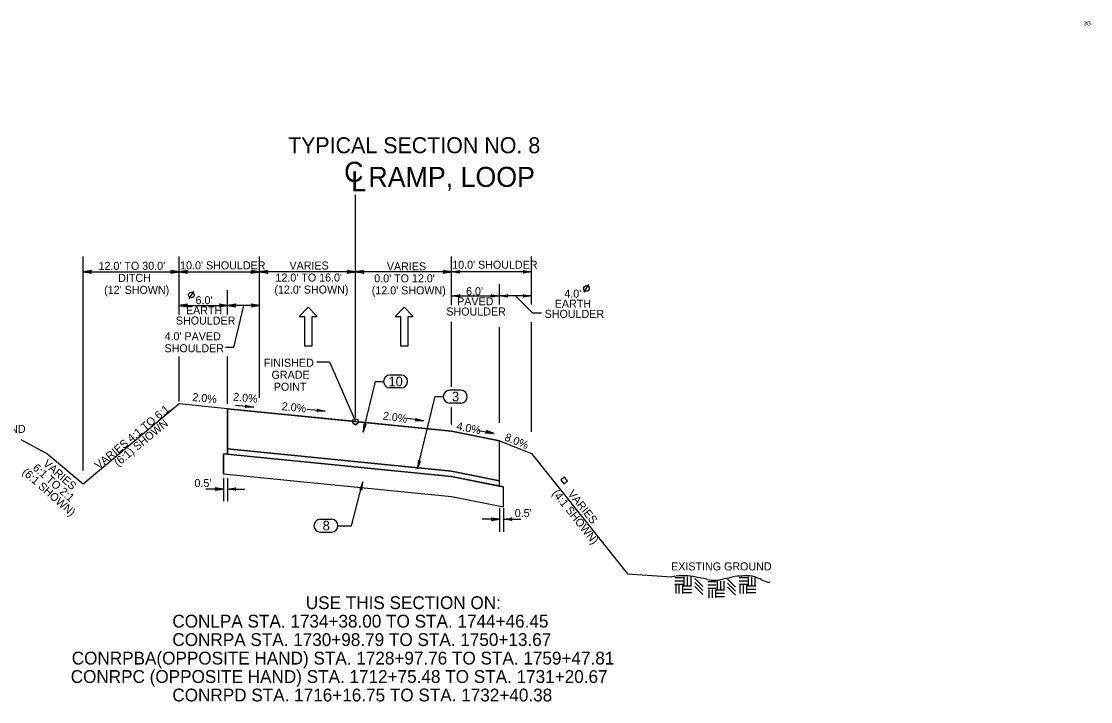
# Model space of a CAD drawing. Extents: x 2003207 to 2014043, y 843846 to 860154.
# Drawn here: x 2013648.6 to 2013782.2, y 844104.4 to 844189.4 of the extents above; entities that cross this region are included whole.
import ezdxf

# ---------------------------------------------------------------- set-up
doc = ezdxf.new("R2010")
doc.units = 0
for name, color, linetype in [('RD_EX_Pavement_Markings', 7, 'Continuous'), ('RD_EX_Road_txCode', 7, 'Continuous'), ('RD_QTY_Base_Course', 7, 'Continuous'), ('RD_QTY_ConcPave', 7, 'Continuous'), ('RD_QTY_Intermediate', 7, 'Continuous'), ('RD_QTY_PermVeg', 7, 'Continuous'), ('RD_QTY_Surf_Course', 7, 'Continuous'), ('RD_SHT_TX', 7, 'Continuous'), ('RD_TX_Misc1', 7, 'Continuous'), ('RD_TX_Misc2', 7, 'Continuous'), ('RD_TX_TypSect', 7, 'Continuous'), ('RD_XS_ExGround', 7, 'Continuous')]:
    doc.layers.add(name, color=color, linetype=linetype)

msp = doc.modelspace()

# ---------------------------------------------------------------- linework, layer by layer
at = {"layer": 'RD_EX_Pavement_Markings'}
for points in [[(2013683.94, 844148.88), (2013684.9, 844148.88), (2013684.9, 844152.54), (2013685.55, 844152.54), (2013684.42, 844153.68), (2013683.29, 844152.54), (2013683.94, 844152.54)], [(2013695.94, 844148.88), (2013696.9, 844148.88), (2013696.9, 844152.54), (2013697.55, 844152.54), (2013696.42, 844153.68), (2013695.29, 844152.54), (2013695.94, 844152.54)]]:
    msp.add_lwpolyline(points, close=True, dxfattribs=at)
at = {"layer": 'RD_EX_Road_txCode'}
msp.add_lwpolyline([(2013715.97, 844132.11), (2013716.35, 844131.64), (2013716.82, 844132.01), (2013716.44, 844132.48)], close=True, dxfattribs=at)
msp.add_circle((2013690.32, 844139.4), 0.35, dxfattribs=at)
at = {"layer": 'RD_QTY_Base_Course'}
for p, q in [((2013673.82, 844132.89), (2013673.82, 844135.39)), ((2013673.82, 844135.39), (2013674.32, 844135.34)), ((2013673.82, 844132.89), (2013702.32, 844130.04)), ((2013708.32, 844131.34), (2013708.82, 844131.24)), ((2013708.82, 844128.74), (2013708.82, 844131.24)), ((2013702.32, 844130.04), (2013708.82, 844128.74))]:
    msp.add_line(p, q, dxfattribs=at)
msp.add_lwpolyline([(2013673.82, 844135.39), (2013673.82, 844132.89), (2013702.32, 844130.04), (2013708.82, 844128.74), (2013708.82, 844131.24), (2013702.32, 844132.54)], close=True, dxfattribs=at)
at = {"layer": 'RD_QTY_ConcPave'}
for p, q in [((2013689.97, 844139.44), (2013674.32, 844141)), ((2013674.32, 844141), (2013674.32, 844136)), ((2013708.32, 844137), (2013702.32, 844138.2)), ((2013708.32, 844132), (2013708.32, 844137)), ((2013674.32, 844136), (2013702.32, 844133.2)), ((2013702.32, 844133.2), (2013708.32, 844132))]:
    msp.add_line(p, q, dxfattribs=at)
msp.add_lwpolyline([(2013702.32, 844138.2), (2013691.56, 844139.28), (2013690.67, 844139.37)], dxfattribs=at)
msp.add_arc((2013690.32, 844139.4), 0.35, 174.2894, 354.2894, dxfattribs=at)
at = {"layer": 'RD_QTY_Intermediate'}
for p, q in [((2013674.32, 844136), (2013674.32, 844141)), ((2013708.32, 844132), (2013708.32, 844137))]:
    msp.add_line(p, q, dxfattribs=at)
at = {"layer": 'RD_QTY_PermVeg'}
for p, q in [((2013668.32, 844141.6), (2013656.32, 844131.6)), ((2013674.32, 844141), (2013668.32, 844141.6)), ((2013708.32, 844137), (2013712.32, 844135.4)), ((2013656.32, 844131.6), (2013651.67, 844135.48)), ((2013712.32, 844135.4), (2013724.32, 844120.4))]:
    msp.add_line(p, q, dxfattribs=at)
at = {"layer": 'RD_QTY_Surf_Course'}
for p, q in [((2013674.32, 844141), (2013702.32, 844138.2)), ((2013702.32, 844138.2), (2013708.32, 844137)), ((2013674.32, 844136), (2013702.32, 844133.2)), ((2013674.32, 844135.34), (2013674.32, 844136)), ((2013702.32, 844133.2), (2013674.32, 844136)), ((2013674.32, 844136), (2013674.32, 844135.34)), ((2013674.32, 844135.34), (2013702.32, 844132.54)), ((2013674.32, 844135.34), (2013702.32, 844132.54)), ((2013702.32, 844133.2), (2013708.32, 844132)), ((2013702.32, 844133.2), (2013702.32, 844133.2)), ((2013702.32, 844132.54), (2013702.32, 844132.54)), ((2013702.32, 844132.54), (2013702.32, 844132.54)), ((2013702.32, 844132.54), (2013702.32, 844132.54)), ((2013702.32, 844132.54), (2013708.32, 844131.34)), ((2013708.32, 844131.34), (2013708.32, 844132))]:
    msp.add_line(p, q, dxfattribs=at)
msp.add_lwpolyline([(2013702.32, 844132.54), (2013708.32, 844131.34), (2013708.32, 844132), (2013702.32, 844133.2)], dxfattribs=at)
at = {"layer": 'RD_TX_Misc2'}
for p, q in [((2013696.03, 844145.21), (2013694.63, 844145.21)), ((2013696.03, 844143.61), (2013694.63, 844143.61)), ((2013703.49, 844143.32), (2013702.09, 844143.32)), ((2013703.49, 844141.72), (2013702.09, 844141.72)), ((2013685.94, 844127.2), (2013687.34, 844127.2)), ((2013685.94, 844125.6), (2013687.34, 844125.6))]:
    msp.add_line(p, q, dxfattribs=at)
for centre, start, end in [((2013694.63, 844144.41), 90, 270), ((2013696.03, 844144.41), 270, 90), ((2013702.09, 844142.52), 90, 270), ((2013703.49, 844142.52), 270, 90), ((2013685.94, 844126.4), 90, 270), ((2013687.34, 844126.4), 270, 90)]:
    msp.add_arc(centre, 0.8, start, end, dxfattribs=at)
at = {"layer": 'RD_TX_TypSect'}
for p, q in [((2013690.32, 844139.9), (2013690.32, 844167.7)), ((2013656.32, 844133.29), (2013656.32, 844160.01)), ((2013668.32, 844152.79), (2013668.32, 844160.01)), ((2013678.32, 844142.36), (2013678.32, 844160.01)), ((2013702.32, 844153.94), (2013702.32, 844160.01)), ((2013712.32, 844154.93), (2013712.32, 844160.01)), ((2013656.32, 844158.1), (2013668.32, 844158.1)), ((2013668.32, 844158.1), (2013678.32, 844158.1)), ((2013690.32, 844158.1), (2013678.32, 844158.1)), ((2013702.32, 844158.1), (2013690.32, 844158.1)), ((2013712.32, 844158.1), (2013702.32, 844158.1)), ((2013708.32, 844154.04), (2013708.32, 844156.55)), ((2013712.32, 844154.04), (2013712.32, 844156.54)), ((2013669.55, 844154.73), (2013670.12, 844155.68)), ((2013674.32, 844152.79), (2013674.32, 844155.81)), ((2013718.9, 844155.56), (2013719.47, 844156.51)), ((2013668.32, 844153.9), (2013674.32, 844153.9)), ((2013678.32, 844153.9), (2013674.32, 844153.9)), ((2013702.32, 844155.1), (2013708.32, 844155.1)), ((2013712.32, 844155.1), (2013708.32, 844155.1)), ((2013702.32, 844143.75), (2013702.32, 844151.84)), ((2013708.32, 844139.26), (2013708.32, 844151.21)), ((2013712.32, 844138.14), (2013712.32, 844151.8)), ((2013668.32, 844141.91), (2013668.32, 844147.55)), ((2013674.32, 844141.62), (2013674.32, 844147.55)), ((2013677.61, 844141.2), (2013675.34, 844141.42)), ((2013686.55, 844140.7), (2013684.28, 844140.93)), ((2013702.32, 844139.04), (2013702.32, 844141.16)), ((2013698.83, 844139.5), (2013696.61, 844139.82)), ((2013705.69, 844138.31), (2013707.64, 844137.92)), ((2013673.82, 844132.34), (2013673.82, 844129.46)), ((2013674.32, 844132.34), (2013674.32, 844129.46)), ((2013673.82, 844130.97), (2013671.65, 844130.97)), ((2013674.32, 844130.97), (2013676.49, 844130.97)), ((2013708.32, 844128.58), (2013708.32, 844125.64)), ((2013708.82, 844128.58), (2013708.82, 844125.64)), ((2013708.32, 844127.21), (2013706.15, 844127.21)), ((2013708.82, 844127.21), (2013710.99, 844127.21))]:
    msp.add_line(p, q, dxfattribs=at)
for points in [[(2013656.32, 844158.1), (2013657.36, 844157.95), (2013657.2, 844158.1), (2013657.36, 844158.25)], [(2013668.32, 844158.1), (2013667.28, 844158.25), (2013667.44, 844158.1), (2013667.28, 844157.95)], [(2013668.32, 844158.1), (2013669.36, 844157.95), (2013669.2, 844158.1), (2013669.36, 844158.25)], [(2013678.32, 844158.1), (2013677.28, 844158.25), (2013677.44, 844158.1), (2013677.28, 844157.95)], [(2013678.32, 844158.1), (2013679.36, 844157.95), (2013679.2, 844158.1), (2013679.36, 844158.25)], [(2013690.32, 844158.1), (2013689.28, 844158.25), (2013689.44, 844158.1), (2013689.28, 844157.95)], [(2013690.32, 844158.1), (2013691.36, 844157.95), (2013691.2, 844158.1), (2013691.36, 844158.25)], [(2013702.32, 844158.1), (2013701.28, 844158.25), (2013701.44, 844158.1), (2013701.28, 844157.95)], [(2013702.32, 844158.1), (2013703.36, 844158.25), (2013703.2, 844158.1), (2013703.36, 844157.95)], [(2013712.32, 844158.1), (2013711.28, 844157.95), (2013711.44, 844158.1), (2013711.28, 844158.25)], [(2013702.32, 844155.1), (2013703.36, 844155.25), (2013703.2, 844155.1), (2013703.36, 844154.95)], [(2013708.32, 844155.1), (2013707.28, 844154.95), (2013707.44, 844155.1), (2013707.28, 844155.25)], [(2013708.32, 844155.1), (2013709.36, 844155.25), (2013709.2, 844155.1), (2013709.36, 844154.95)], [(2013712.32, 844155.1), (2013711.28, 844154.95), (2013711.44, 844155.1), (2013711.28, 844155.25)], [(2013668.32, 844153.9), (2013669.36, 844153.75), (2013669.2, 844153.9), (2013669.36, 844154.05)], [(2013674.32, 844153.9), (2013673.28, 844154.05), (2013673.44, 844153.9), (2013673.28, 844153.75)], [(2013674.32, 844153.9), (2013675.36, 844153.75), (2013675.2, 844153.9), (2013675.36, 844154.05)], [(2013678.32, 844153.9), (2013677.28, 844154.05), (2013677.44, 844153.9), (2013677.28, 844153.75)], [(2013677.61, 844141.2), (2013676.56, 844141.15), (2013676.74, 844141.28), (2013676.59, 844141.45)], [(2013686.55, 844140.7), (2013685.5, 844140.66), (2013685.68, 844140.79), (2013685.53, 844140.96)], [(2013698.83, 844139.5), (2013697.8, 844139.5), (2013697.98, 844139.62), (2013697.84, 844139.79)], [(2013691.27, 844138.1), (2013691.66, 844139.07), (2013691.48, 844138.95), (2013691.37, 844139.14)], [(2013707.64, 844137.92), (2013706.65, 844138.27), (2013706.78, 844138.09), (2013706.59, 844137.98)], [(2013698.08, 844133.5), (2013698.47, 844134.47), (2013698.29, 844134.35), (2013698.18, 844134.54)], [(2013691.25, 844131.9), (2013690.85, 844130.93), (2013691.03, 844131.05), (2013691.14, 844130.85)], [(2013673.82, 844130.97), (2013672.78, 844131.12), (2013672.94, 844130.97), (2013672.78, 844130.82)], [(2013674.32, 844130.97), (2013675.36, 844131.12), (2013675.2, 844130.97), (2013675.36, 844130.82)], [(2013708.32, 844127.21), (2013707.28, 844127.36), (2013707.44, 844127.21), (2013707.28, 844127.06)], [(2013708.82, 844127.21), (2013709.86, 844127.36), (2013709.7, 844127.21), (2013709.86, 844127.06)]]:
    msp.add_lwpolyline(points, close=True, dxfattribs=at)
for points in [[(2013676.32, 844153.9), (2013675.08, 844148.66), (2013674.09, 844148.66)], [(2013713.57, 844152.95), (2013712.48, 844152.95), (2013710.32, 844155.1)], [(2013685.5, 844146.85), (2013687.07, 844146.85), (2013690.32, 844139.4)], [(2013691.27, 844138.1), (2013692.82, 844144.41), (2013693.83, 844144.41)], [(2013698.08, 844133.5), (2013700.29, 844142.52), (2013701.29, 844142.52)], [(2013688.14, 844126.4), (2013689.81, 844126.4), (2013691.25, 844131.9)]]:
    msp.add_lwpolyline(points, dxfattribs=at)
for centre in [(2013669.83, 844155.21), (2013719.19, 844156.03)]:
    msp.add_circle(centre, 0.35, dxfattribs=at)
at = {"layer": 'RD_XS_ExGround'}
for p, q in [((2013648.54, 844137.15), (2013651.67, 844135.48)), ((2013724.32, 844120.4), (2013729.85, 844120.02)), ((2013731.27, 844119.91), (2013730.22, 844119.91)), ((2013731.27, 844119.49), (2013730.22, 844119.49)), ((2013731.36, 844120), (2013731.36, 844118.96)), ((2013731.78, 844120), (2013731.78, 844118.96)), ((2013732.2, 844120), (2013732.2, 844118.96)), ((2013733.72, 844118.81), (2013732.72, 844119.81)), ((2013733.72, 844118.31), (2013732.72, 844119.31)), ((2013735.4, 844119.39), (2013734.36, 844119.39)), ((2013735.5, 844119.48), (2013735.5, 844118.44)), ((2013735.91, 844119.48), (2013735.91, 844118.44)), ((2013736.33, 844119.48), (2013736.33, 844118.44)), ((2013737.79, 844118.74), (2013736.79, 844119.74)), ((2013737.79, 844118.24), (2013736.79, 844119.24)), ((2013739.29, 844119.9), (2013738.25, 844119.9)), ((2013739.29, 844119.48), (2013738.25, 844119.48)), ((2013739.39, 844120), (2013739.39, 844118.96)), ((2013739.81, 844120), (2013739.81, 844118.96)), ((2013740.22, 844120), (2013740.22, 844118.96)), ((2013731.27, 844119.07), (2013730.22, 844119.07)), ((2013730.33, 844118.97), (2013730.33, 844117.93)), ((2013730.74, 844118.97), (2013730.74, 844117.93)), ((2013731.16, 844118.97), (2013731.16, 844117.93)), ((2013732.31, 844118.86), (2013731.27, 844118.86)), ((2013732.31, 844118.45), (2013731.27, 844118.45)), ((2013732.31, 844118.03), (2013731.27, 844118.03)), ((2013733.72, 844117.81), (2013732.72, 844118.81)), ((2013735.4, 844118.97), (2013734.36, 844118.97)), ((2013735.4, 844118.55), (2013734.36, 844118.55)), ((2013734.46, 844118.45), (2013734.46, 844117.41)), ((2013734.88, 844118.45), (2013734.88, 844117.41)), ((2013735.3, 844118.45), (2013735.3, 844117.41)), ((2013736.44, 844118.35), (2013735.4, 844118.35)), ((2013736.44, 844117.93), (2013735.4, 844117.93)), ((2013737.79, 844117.74), (2013736.79, 844118.74)), ((2013739.29, 844119.07), (2013738.25, 844119.07)), ((2013738.35, 844118.96), (2013738.35, 844117.92)), ((2013738.77, 844118.96), (2013738.77, 844117.92)), ((2013739.19, 844118.96), (2013739.19, 844117.92)), ((2013740.33, 844118.86), (2013739.29, 844118.86)), ((2013740.33, 844118.44), (2013739.29, 844118.44)), ((2013740.33, 844118.03), (2013739.29, 844118.03)), ((2013736.44, 844117.51), (2013735.4, 844117.51))]:
    msp.add_line(p, q, dxfattribs=at)
msp.add_lwpolyline([(2013742.08, 844119.29), (2013741.86, 844119.32), (2013741.64, 844119.4), (2013741.35, 844119.51), (2013741.09, 844119.62), (2013740.87, 844119.76), (2013740.69, 844119.8), (2013740.43, 844119.94), (2013740.21, 844120.02), (2013739.88, 844120.09), (2013739.63, 844120.13), (2013739.33, 844120.13), (2013739, 844120.13), (2013738.82, 844120.13), (2013738.64, 844120.09), (2013738.42, 844120.09), (2013738.2, 844120.09), (2013738.01, 844120.09), (2013737.72, 844120.05), (2013737.54, 844120.02), (2013737.21, 844119.94), (2013736.92, 844119.87), (2013736.62, 844119.8), (2013736.44, 844119.76), (2013736.11, 844119.69), (2013735.82, 844119.62), (2013735.6, 844119.58), (2013735.42, 844119.58), (2013735.2, 844119.58), (2013734.98, 844119.58), (2013734.76, 844119.58), (2013734.54, 844119.62), (2013734.35, 844119.65), (2013734.1, 844119.76), (2013733.84, 844119.8), (2013733.55, 844119.84), (2013733.29, 844119.91), (2013733.04, 844119.94), (2013732.74, 844120.02), (2013732.45, 844120.05), (2013732.16, 844120.09), (2013731.83, 844120.13), (2013731.54, 844120.13), (2013731.32, 844120.16), (2013731.13, 844120.16), (2013730.95, 844120.13), (2013730.66, 844120.13), (2013730.4, 844120.09), (2013730.14, 844120.05), (2013729.85, 844120.02)], dxfattribs=at)

# ---------------------------------------------------------------- texts
at = {"layer": 'RD_EX_Road_txCode'}
for s, p in [('USE THIS SECTION ON:', (2013684.12, 844115.99)), ('CONLPA STA. 1734+38.00 TO STA. 1744+46.45', (2013667.45, 844113.68)), ('CONRPA STA. 1730+98.79 TO STA. 1750+13.67', (2013667.45, 844111.38)), ('CONRPBA(OPPOSITE HAND) STA. 1728+97.76 TO STA. 1759+47.81 ', (2013654.88, 844109.07)), ('CONRPC (OPPOSITE HAND) STA. 1712+75.48 TO STA. 1731+20.67', (2013654.75, 844106.77)), ('CONRPD STA. 1716+16.75 TO STA. 1732+40.38', (2013667.45, 844104.46))]:
    msp.add_text(s, height=1.6, dxfattribs=at).set_placement(p)
at = {"layer": 'RD_SHT_TX'}
msp.add_text('3G', height=0.5, dxfattribs=at).set_placement((2013781.32, 844188.87))
at = {"layer": 'RD_TX_Misc1'}
for s, p in [('C', (2013688.91, 844169.34)), ('RAMP, LOOP', (2013691.94, 844168.71)), ('L', (2013689.79, 844168.16))]:
    msp.add_text(s, height=2.5, dxfattribs=at).set_placement(p)
at = {"layer": 'RD_TX_Misc2'}
for s, p in [('10', (2013694.45, 844143.82)), ('3', (2013702.38, 844141.93)), ('8', (2013686.23, 844125.82))]:
    msp.add_text(s, height=1.2, dxfattribs=at).set_placement(p)
at = {"layer": 'RD_TX_TypSect'}
for s, height, p in [('TYPICAL SECTION NO. 8', 2, (2013681.9, 844172.91)), ("12.0' TO 30.0'", 1, (2013658.23, 844158.35)), ("10.0' SHOULDER", 1, (2013668.42, 844158.41)), ('VARIES', 1, (2013682.08, 844158.39)), ('VARIES', 1, (2013694.24, 844158.29)), ("10.0' SHOULDER", 1, (2013702.41, 844158.49)), ("12.0' TO 16.0'", 1, (2013680.33, 844156.89)), ('DITCH', 1, (2013660.68, 844156.85)), ("0.0' TO 12.0'", 1, (2013692.67, 844156.79)), ("(12' SHOWN)", 1, (2013658.93, 844155.35)), ("(12.0' SHOWN)", 1, (2013680.2, 844155.39)), ("(12.0' SHOWN)", 1, (2013692.36, 844155.29)), ("6.0'", 1, (2013704.14, 844155.18)), ("4.0'", 1, (2013716.42, 844154.89)), ("6.0'", 1, (2013670.35, 844154.06)), ('PAVED', 1, (2013703.02, 844153.92)), ('EARTH', 1, (2013715.22, 844153.62)), ('SHOULDER', 1, (2013667.89, 844151.52)), ('EARTH', 1, (2013669.15, 844152.79)), ('SHOULDER', 1, (2013701.68, 844152.65)), ('SHOULDER', 1, (2013713.96, 844152.35)), ("4.0' PAVED", 1, (2013666.48, 844149.56)), ('SHOULDER', 1, (2013666.47, 844148.06)), ('FINISHED', 1, (2013678.87, 844146.25)), ('GRADE', 1, (2013679.84, 844144.75)), ('POINT', 1, (2013680.12, 844143.25)), ('EXISTING GROUND', 1, (2013636.56, 844137.99)), ("0.5'", 1, (2013670.21, 844131.23)), ("0.5'", 1, (2013710.22, 844127.48)), ('EXISTING GROUND', 1, (2013729.75, 844120.82))]:
    msp.add_text(s, height=height, dxfattribs=at).set_placement(p)
for s, rotation, p in [('2.0%', 354.2894, (2013669.91, 844141.99)), ('2.0%', 354.2894, (2013675.01, 844142.03)), ('VARIES 4:1 TO 6:1', 39.8056, (2013658.28, 844133.38)), ('2.0%', 354.2894, (2013681.08, 844140.84)), ('2.0%', 351.8393, (2013693.7, 844139.67)), (' (6:1) SHOWN', 39.8056, (2013660.39, 844133.49)), ('4.0%', 348.6901, (2013702.89, 844138.4)), ('8.0%', 338.1986, (2013708.87, 844137.08)), ('6:1 TO 2:1', 318.689, (2013649.92, 844133.49)), ('VARIES ', 318.689, (2013651.23, 844134.03)), ('(6:1 SHOWN)', 318.689, (2013648.6, 844132.96)), ('(4:1 SHOWN)', 308.6598, (2013714.83, 844130.42)), ('VARIES', 308.6598, (2013716.79, 844130.37))]:
    msp.add_text(s, height=1, rotation=rotation, dxfattribs=at).set_placement(p)

doc.saveas('drawing.dxf')
